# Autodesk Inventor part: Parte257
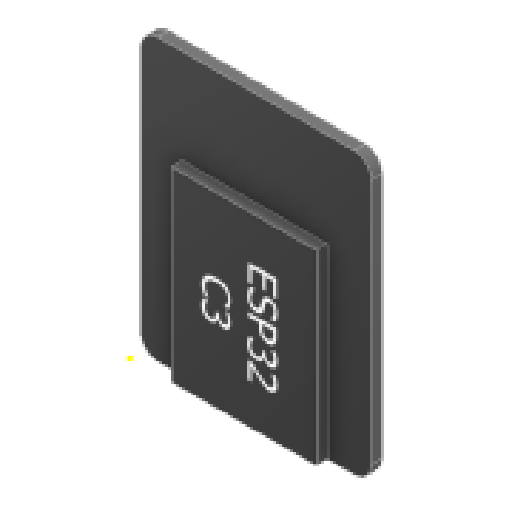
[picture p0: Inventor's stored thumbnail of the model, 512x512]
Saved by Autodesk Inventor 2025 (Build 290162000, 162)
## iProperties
Created: 2025-05
Part Number: Parte257
Material: Generico
Document SubType Name: Modeling
Designer: R5800u
Density: 1 g/cm^3
Appearance: Default
Author: R5800u
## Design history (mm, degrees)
feature "Corps1"
sketch "Schizzo1"
  geometry: L1 (9.446, -2.633)-(9.419, -14.205); L2 (9.419, -14.205)-(1.224, -14.186); L3 (1.224, -14.186)-(1.252, -2.614); L4 (1.252, -2.614)-(9.446, -2.633); 1 further point
  constraints: 3 other
node "Solido1"
